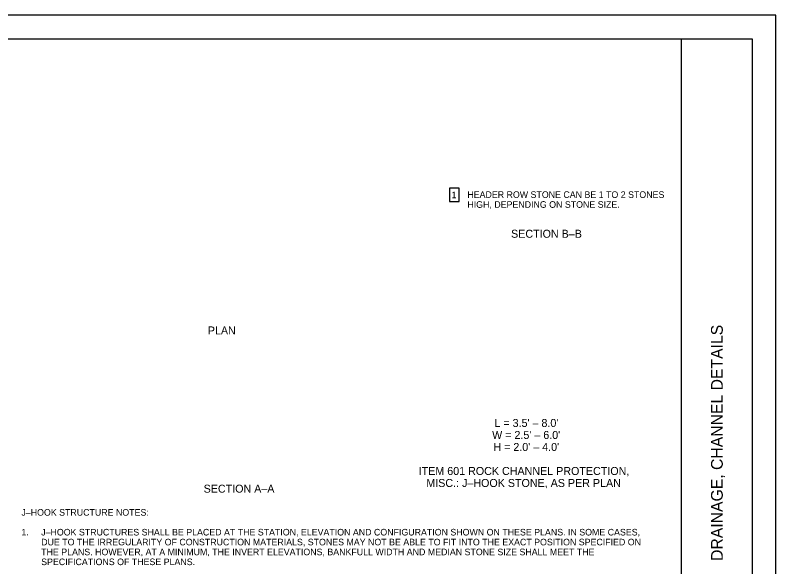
# Model space of a CAD drawing. Extents: x 0 to 34, y 0 to 22.
# Drawn here: x 17.86 to 34, y 10.28 to 22 of the extents above; entities that cross this region are included whole.
import ezdxf

# ---------------------------------------------------------------- set-up
doc = ezdxf.new("R2010")
doc.units = 0
for name, color, linetype in [('CS-ALGN-CNTR', 7, 'Continuous'), ('CS-ALGN-TEXT', 7, 'Continuous'), ('CS-ANNO', 7, 'Continuous'), ('CS-ANNO-TABL', 7, 'Continuous')]:
    doc.layers.add(name, color=color, linetype=linetype)

msp = doc.modelspace()

# ---------------------------------------------------------------- linework, layer by layer
at = {"layer": 'CS-ALGN-CNTR'}
msp.add_lwpolyline([(0, 0), (34, 0), (34, 22), (0, 22)], close=True, dxfattribs=at)
at = {"layer": 'CS-ALGN-TEXT'}
msp.add_line((32, 0.5), (32, 21.5), dxfattribs=at)
msp.add_lwpolyline([(1.5, 21.5), (33.5, 21.5), (33.5, 0.5), (1.5, 0.5)], close=True, dxfattribs=at)
at = {"layer": 'CS-ANNO-TABL'}
msp.add_lwpolyline([(27.077, 18.043), (27.281, 18.043), (27.281, 18.324), (27.077, 18.324)], close=True, dxfattribs=at)

# ---------------------------------------------------------------- texts
at = {"layer": 'CS-ANNO'}
msp.add_text('DRAINAGE, CHANNEL DETAILS', height=0.25, rotation=90, dxfattribs=at).set_placement((32.875, 10.408))
at = {"layer": 'CS-ANNO-TABL'}
for s, height, p in [('1', 0.14, (27.118, 18.113)), ('HEADER ROW STONE CAN BE 1 TO 2 STONES', 0.14, (27.453, 18.119)), ('HIGH, DEPENDING ON STONE SIZE.', 0.14, (27.453, 17.909)), ('SECTION B‒B', 0.17, (28.381, 17.273)), ('PLAN', 0.17, (21.944, 15.218)), ("L = 3.5' ‒ 8.0'", 0.17, (28.028, 13.254)), ("W = 2.5' ‒ 6.0'", 0.17, (27.979, 12.999)), ("H = 2.0' ‒ 4.0'", 0.17, (28.006, 12.744)), ('ITEM 601 ROCK CHANNEL PROTECTION,', 0.17, (26.42, 12.234)), ('MISC.: J‒HOOK STONE, AS PER PLAN', 0.17, (26.582, 11.979)), ('SECTION A‒A', 0.17, (21.855, 11.858)), ('J‒HOOK STRUCTURE NOTES:', 0.14, (17.987, 11.369)), ('1.', 0.14, (17.987, 10.949)), ('J‒HOOK STRUCTURES SHALL BE PLACED AT THE STATION, ELEVATION AND CONFIGURATION SHOWN ON THESE PLANS. IN SOME CASES, ', 0.14, (18.407, 10.949)), ('DUE TO THE IRREGULARITY OF CONSTRUCTION MATERIALS, STONES MAY NOT BE ABLE TO FIT INTO THE EXACT POSITION SPECIFIED ON ', 0.14, (18.407, 10.739)), ('THE PLANS. HOWEVER, AT A MINIMUM, THE INVERT ELEVATIONS, BANKFULL WIDTH AND MEDIAN STONE SIZE SHALL MEET THE ', 0.14, (18.407, 10.529)), ('SPECIFICATIONS OF THESE PLANS.', 0.14, (18.407, 10.319))]:
    msp.add_text(s, height=height, dxfattribs=at).set_placement(p)

doc.saveas('drawing.dxf')
